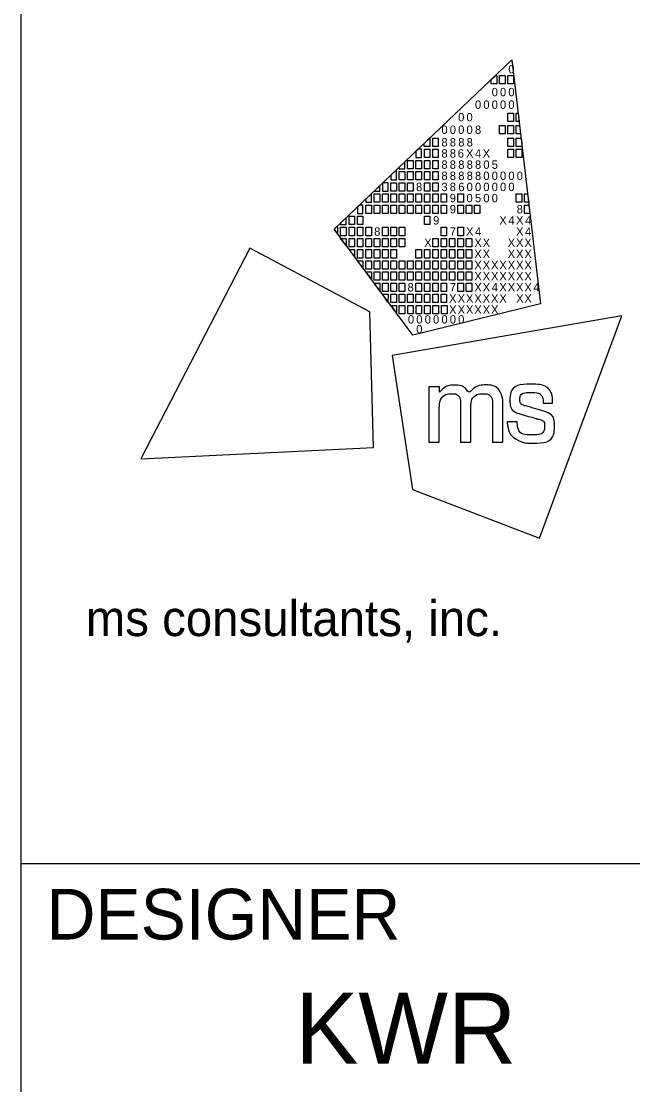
# Model space of a CAD drawing. Extents: x -0.2 to 34, y -4.4 to 17.6.
# Drawn here: x 32 to 33.207, y -2.337 to -0.238 of the extents above; entities that cross this region are included whole.
import ezdxf

# ---------------------------------------------------------------- set-up
doc = ezdxf.new("R2010")
doc.units = 0
doc.layers.add('SH_Border', color=7, linetype='Continuous')
doc.layers.add('SH_Data', color=7, linetype='Continuous')

msp = doc.modelspace()

# ---------------------------------------------------------------- linework, layer by layer
at = {"layer": 'SH_Border'}
for p, q in [((32, -3.9004), (32, 17.0996)), ((32, -1.9004), (33.5, -1.9004))]:
    msp.add_line(p, q, dxfattribs=at)
at = {"layer": 'SH_Data'}
for p, q in [((32.6175, -0.6485), (32.9688, -0.3143)), ((32.9688, -0.3143), (32.9688, -0.3143)), ((32.9688, -0.3143), (33.0253, -0.7953)), ((32.773, -0.8574), (32.6175, -0.6485)), ((33.0253, -0.7953), (32.773, -0.8574)), ((32.75, -0.9004), (32.75, -0.9004))]:
    msp.add_line(p, q, dxfattribs=at)
for points in [[(32.9279, -0.3532), (32.9369, -0.3446), (32.9389, -0.3446), (32.9389, -0.3612), (32.9279, -0.3612)], [(32.9444, -0.3446), (32.9554, -0.3446), (32.9554, -0.3612), (32.9444, -0.3612)], [(32.9609, -0.3446), (32.9719, -0.3446), (32.9719, -0.3612), (32.9609, -0.3612)], [(32.9606, -0.419), (32.9716, -0.419), (32.9716, -0.4355), (32.9606, -0.4355)], [(32.9771, -0.419), (32.9811, -0.419), (32.983, -0.4355), (32.9771, -0.4355)], [(32.9441, -0.4437), (32.9551, -0.4437), (32.9551, -0.4602), (32.9441, -0.4602)], [(32.9606, -0.4437), (32.9716, -0.4437), (32.9716, -0.4602), (32.9606, -0.4602)], [(32.9771, -0.4437), (32.984, -0.4437), (32.9859, -0.4602), (32.9771, -0.4602)], [(32.7953, -0.4793), (32.8064, -0.4688), (32.8064, -0.485), (32.7953, -0.485)], [(32.8123, -0.4685), (32.8233, -0.4685), (32.8233, -0.485), (32.8123, -0.485)], [(32.9606, -0.4685), (32.9716, -0.4685), (32.9716, -0.485), (32.9606, -0.485)], [(32.9771, -0.4685), (32.9869, -0.4685), (32.9881, -0.4786), (32.9881, -0.485), (32.9771, -0.485)], [(32.7958, -0.4905), (32.8068, -0.4905), (32.8068, -0.507), (32.7958, -0.507)], [(32.8123, -0.4905), (32.8233, -0.4905), (32.8233, -0.507), (32.8123, -0.507)], [(32.9606, -0.4905), (32.9716, -0.4905), (32.9716, -0.507), (32.9606, -0.507)], [(32.9771, -0.4905), (32.9881, -0.4905), (32.9881, -0.507), (32.9771, -0.507)], [(32.7627, -0.5125), (32.7737, -0.5125), (32.7737, -0.529), (32.7627, -0.529)], [(32.7793, -0.5125), (32.7903, -0.5125), (32.7903, -0.529), (32.7793, -0.529)], [(32.7958, -0.5125), (32.8068, -0.5125), (32.8068, -0.529), (32.7958, -0.529)], [(32.8123, -0.5125), (32.8233, -0.5125), (32.8233, -0.529), (32.8123, -0.529)], [(32.7462, -0.5346), (32.7572, -0.5346), (32.7572, -0.5511), (32.7462, -0.5511)], [(32.7627, -0.5346), (32.7737, -0.5346), (32.7737, -0.5511), (32.7627, -0.5511)], [(32.7793, -0.5346), (32.7903, -0.5346), (32.7903, -0.5511), (32.7793, -0.5511)], [(32.7958, -0.5346), (32.8068, -0.5346), (32.8068, -0.5511), (32.7958, -0.5511)], [(32.8123, -0.5346), (32.8233, -0.5346), (32.8233, -0.5511), (32.8123, -0.5511)], [(32.7297, -0.5566), (32.7407, -0.5566), (32.7407, -0.5731), (32.7297, -0.5731)], [(32.7462, -0.5566), (32.7572, -0.5566), (32.7572, -0.5731), (32.7462, -0.5731)], [(32.7627, -0.5566), (32.7737, -0.5566), (32.7737, -0.5731), (32.7627, -0.5731)], [(32.7958, -0.5566), (32.8068, -0.5566), (32.8068, -0.5731), (32.7958, -0.5731)], [(32.8123, -0.5566), (32.8233, -0.5566), (32.8233, -0.5731), (32.8123, -0.5731)], [(32.6967, -0.5786), (32.7077, -0.5786), (32.7077, -0.5951), (32.6967, -0.5951)], [(32.7132, -0.5786), (32.7242, -0.5786), (32.7242, -0.5951), (32.7132, -0.5951)], [(32.7297, -0.5786), (32.7407, -0.5786), (32.7407, -0.5951), (32.7297, -0.5951)], [(32.7462, -0.5786), (32.7572, -0.5786), (32.7572, -0.5951), (32.7462, -0.5951)], [(32.7627, -0.5786), (32.7737, -0.5786), (32.7737, -0.5951), (32.7627, -0.5951)], [(32.7793, -0.5786), (32.7903, -0.5786), (32.7903, -0.5951), (32.7793, -0.5951)], [(32.7958, -0.5786), (32.8068, -0.5786), (32.8068, -0.5951), (32.7958, -0.5951)], [(32.8123, -0.5786), (32.8233, -0.5786), (32.8233, -0.5951), (32.8123, -0.5951)], [(32.8288, -0.5786), (32.8398, -0.5786), (32.8398, -0.5951), (32.8288, -0.5951)], [(32.8618, -0.5786), (32.8728, -0.5786), (32.8728, -0.5951), (32.8618, -0.5951)], [(32.9771, -0.5786), (32.9881, -0.5786), (32.9881, -0.5951), (32.9771, -0.5951)], [(32.9935, -0.5786), (32.9998, -0.5786), (33.0018, -0.5951), (32.9935, -0.5951)], [(32.6802, -0.6006), (32.6912, -0.6006), (32.6912, -0.6171), (32.6802, -0.6171)], [(32.6967, -0.6006), (32.7077, -0.6006), (32.7077, -0.6171), (32.6967, -0.6171)], [(32.7132, -0.6006), (32.7242, -0.6006), (32.7242, -0.6171), (32.7132, -0.6171)], [(32.7297, -0.6006), (32.7407, -0.6006), (32.7407, -0.6171), (32.7297, -0.6171)], [(32.7462, -0.6006), (32.7572, -0.6006), (32.7572, -0.6171), (32.7462, -0.6171)], [(32.7627, -0.6006), (32.7737, -0.6006), (32.7737, -0.6171), (32.7627, -0.6171)], [(32.7793, -0.6006), (32.7903, -0.6006), (32.7903, -0.6171), (32.7793, -0.6171)], [(32.7958, -0.6006), (32.8068, -0.6006), (32.8068, -0.6171), (32.7958, -0.6171)], [(32.8123, -0.6006), (32.8233, -0.6006), (32.8233, -0.6171), (32.8123, -0.6171)], [(32.8288, -0.6006), (32.8398, -0.6006), (32.8398, -0.6171), (32.8288, -0.6171)], [(32.8618, -0.6006), (32.8728, -0.6006), (32.8728, -0.6171), (32.8618, -0.6171)], [(32.8783, -0.6006), (32.8893, -0.6006), (32.8893, -0.6171), (32.8783, -0.6171)], [(32.8947, -0.6006), (32.9057, -0.6006), (32.9057, -0.6171), (32.8947, -0.6171)], [(32.9935, -0.6006), (33.0024, -0.6006), (33.0044, -0.6171), (32.9935, -0.6171)], [(32.6471, -0.6226), (32.6581, -0.6226), (32.6581, -0.6391), (32.6471, -0.6391)], [(32.6637, -0.6226), (32.6747, -0.6226), (32.6747, -0.6391), (32.6637, -0.6391)], [(32.7958, -0.6226), (32.8068, -0.6226), (32.8068, -0.6391), (32.7958, -0.6391)], [(32.6306, -0.6446), (32.6416, -0.6446), (32.6416, -0.6612), (32.6306, -0.6612)], [(32.6471, -0.6446), (32.6581, -0.6446), (32.6581, -0.6612), (32.6471, -0.6612)], [(32.6637, -0.6446), (32.6747, -0.6446), (32.6747, -0.6612), (32.6637, -0.6612)], [(32.6802, -0.6446), (32.6912, -0.6446), (32.6912, -0.6612), (32.6802, -0.6612)], [(32.7132, -0.6446), (32.7242, -0.6446), (32.7242, -0.6612), (32.7132, -0.6612)], [(32.7297, -0.6446), (32.7407, -0.6446), (32.7407, -0.6612), (32.7297, -0.6612)], [(32.7462, -0.6446), (32.7572, -0.6446), (32.7572, -0.6612), (32.7462, -0.6612)], [(32.8288, -0.6446), (32.8398, -0.6446), (32.8398, -0.6612), (32.8288, -0.6612)], [(32.8618, -0.6446), (32.8728, -0.6446), (32.8728, -0.6612), (32.8618, -0.6612)], [(32.6306, -0.6667), (32.6416, -0.6667), (32.6416, -0.6804)], [(32.6471, -0.6667), (32.6581, -0.6667), (32.6581, -0.6832), (32.6471, -0.6832)], [(32.6637, -0.6667), (32.6747, -0.6667), (32.6747, -0.6832), (32.6637, -0.6832)], [(32.6802, -0.6667), (32.6912, -0.6667), (32.6912, -0.6832), (32.6802, -0.6832)], [(32.6967, -0.6667), (32.7077, -0.6667), (32.7077, -0.6832), (32.6967, -0.6832)], [(32.7132, -0.6667), (32.7242, -0.6667), (32.7242, -0.6832), (32.7132, -0.6832)], [(32.7297, -0.6667), (32.7407, -0.6667), (32.7407, -0.6832), (32.7297, -0.6832)], [(32.7462, -0.6667), (32.7572, -0.6667), (32.7572, -0.6832), (32.7462, -0.6832)], [(32.8123, -0.6667), (32.8233, -0.6667), (32.8233, -0.6832), (32.8123, -0.6832)], [(32.8288, -0.6667), (32.8398, -0.6667), (32.8398, -0.6832), (32.8288, -0.6832)], [(32.8453, -0.6667), (32.8563, -0.6667), (32.8563, -0.6832), (32.8453, -0.6832)], [(32.8618, -0.6667), (32.8728, -0.6667), (32.8728, -0.6832), (32.8618, -0.6832)], [(32.8783, -0.6667), (32.8893, -0.6667), (32.8893, -0.6832), (32.8783, -0.6832)], [(32.6471, -0.6887), (32.6581, -0.6887), (32.6581, -0.7024)], [(32.6637, -0.6887), (32.6747, -0.6887), (32.6747, -0.7052), (32.6637, -0.7052)], [(32.6802, -0.6887), (32.6912, -0.6887), (32.6912, -0.7052), (32.6802, -0.7052)], [(32.6967, -0.6887), (32.7077, -0.6887), (32.7077, -0.7052), (32.6967, -0.7052)], [(32.7132, -0.6887), (32.7242, -0.6887), (32.7242, -0.7052), (32.7132, -0.7052)], [(32.7297, -0.6887), (32.7407, -0.6887), (32.7407, -0.7052), (32.7297, -0.7052)], [(32.7793, -0.6887), (32.7903, -0.6887), (32.7903, -0.7052), (32.7793, -0.7052)], [(32.7958, -0.6887), (32.8068, -0.6887), (32.8068, -0.7052), (32.7958, -0.7052)], [(32.8123, -0.6887), (32.8233, -0.6887), (32.8233, -0.7052), (32.8123, -0.7052)], [(32.8288, -0.6887), (32.8398, -0.6887), (32.8398, -0.7052), (32.8288, -0.7052)], [(32.8453, -0.6887), (32.8563, -0.6887), (32.8563, -0.7052), (32.8453, -0.7052)], [(32.8618, -0.6887), (32.8728, -0.6887), (32.8728, -0.7052), (32.8618, -0.7052)], [(32.8783, -0.6887), (32.8893, -0.6887), (32.8893, -0.7052), (32.8783, -0.7052)], [(32.6637, -0.7107), (32.6747, -0.7107), (32.6747, -0.7245)], [(32.6747, -0.7107), (32.6747, -0.7107), (32.6747, -0.7107)], [(32.6802, -0.7107), (32.6912, -0.7107), (32.6912, -0.7272), (32.6802, -0.7272)], [(32.6967, -0.7107), (32.7077, -0.7107), (32.7077, -0.7272), (32.6967, -0.7272)], [(32.7132, -0.7107), (32.7242, -0.7107), (32.7242, -0.7272), (32.7132, -0.7272)], [(32.7297, -0.7107), (32.7407, -0.7107), (32.7407, -0.7272), (32.7297, -0.7272)], [(32.7462, -0.7107), (32.7572, -0.7107), (32.7572, -0.7272), (32.7462, -0.7272)], [(32.7627, -0.7107), (32.7737, -0.7107), (32.7737, -0.7272), (32.7627, -0.7272)], [(32.7793, -0.7107), (32.7903, -0.7107), (32.7903, -0.7272), (32.7793, -0.7272)], [(32.7958, -0.7107), (32.8068, -0.7107), (32.8068, -0.7272), (32.7958, -0.7272)], [(32.8123, -0.7107), (32.8233, -0.7107), (32.8233, -0.7272), (32.8123, -0.7272)], [(32.8288, -0.7107), (32.8398, -0.7107), (32.8398, -0.7272), (32.8288, -0.7272)], [(32.8453, -0.7107), (32.8563, -0.7107), (32.8563, -0.7272), (32.8453, -0.7272)], [(32.8618, -0.7107), (32.8728, -0.7107), (32.8728, -0.7272), (32.8618, -0.7272)], [(32.8783, -0.7107), (32.8893, -0.7107), (32.8893, -0.7272), (32.8783, -0.7272)], [(32.6802, -0.7327), (32.6912, -0.7327), (32.6912, -0.7465)], [(32.6967, -0.7327), (32.7077, -0.7327), (32.7077, -0.7492), (32.6967, -0.7492)], [(32.7132, -0.7327), (32.7242, -0.7327), (32.7242, -0.7492), (32.7132, -0.7492)], [(32.7297, -0.7327), (32.7407, -0.7327), (32.7407, -0.7492), (32.7297, -0.7492)], [(32.7462, -0.7327), (32.7572, -0.7327), (32.7572, -0.7492), (32.7462, -0.7492)], [(32.7627, -0.7327), (32.7737, -0.7327), (32.7737, -0.7492), (32.7627, -0.7492)], [(32.7793, -0.7327), (32.7903, -0.7327), (32.7903, -0.7492), (32.7793, -0.7492)], [(32.7958, -0.7327), (32.8068, -0.7327), (32.8068, -0.7492), (32.7958, -0.7492)], [(32.8123, -0.7327), (32.8233, -0.7327), (32.8233, -0.7492), (32.8123, -0.7492)], [(32.8288, -0.7327), (32.8398, -0.7327), (32.8398, -0.7492), (32.8288, -0.7492)], [(32.8453, -0.7327), (32.8563, -0.7327), (32.8563, -0.7492), (32.8453, -0.7492)], [(32.8618, -0.7327), (32.8728, -0.7327), (32.8728, -0.7492), (32.8618, -0.7492)], [(32.8783, -0.7327), (32.8893, -0.7327), (32.8893, -0.7492), (32.8783, -0.7492)], [(32.7077, -0.7699), (32.6965, -0.7547), (32.7077, -0.7547)], [(32.7132, -0.7547), (32.7242, -0.7547), (32.7242, -0.7712), (32.7132, -0.7712)], [(32.7297, -0.7547), (32.7407, -0.7547), (32.7407, -0.7712), (32.7297, -0.7712)], [(32.7462, -0.7547), (32.7572, -0.7547), (32.7572, -0.7712), (32.7462, -0.7712)], [(32.7793, -0.7547), (32.7903, -0.7547), (32.7903, -0.7712), (32.7793, -0.7712)], [(32.7958, -0.7547), (32.8068, -0.7547), (32.8068, -0.7712), (32.7958, -0.7712)], [(32.8123, -0.7547), (32.8233, -0.7547), (32.8233, -0.7712), (32.8123, -0.7712)], [(32.8288, -0.7547), (32.8398, -0.7547), (32.8398, -0.7712), (32.8288, -0.7712)], [(32.8618, -0.7547), (32.8728, -0.7547), (32.8728, -0.7712), (32.8618, -0.7712)], [(32.8783, -0.7547), (32.8893, -0.7547), (32.8893, -0.7712), (32.8783, -0.7712)], [(32.724, -0.7922), (32.7132, -0.7767), (32.7242, -0.7767)], [(32.7297, -0.7768), (32.7407, -0.7768), (32.7407, -0.7933), (32.7297, -0.7933)], [(32.7462, -0.7768), (32.7572, -0.7768), (32.7572, -0.7933), (32.7462, -0.7933)], [(32.7627, -0.7768), (32.7737, -0.7768), (32.7737, -0.7933), (32.7627, -0.7933)], [(32.7793, -0.7768), (32.7903, -0.7768), (32.7903, -0.7933), (32.7793, -0.7933)], [(32.7958, -0.7768), (32.8068, -0.7768), (32.8068, -0.7933), (32.7958, -0.7933)], [(32.8123, -0.7768), (32.8233, -0.7768), (32.8233, -0.7933), (32.8123, -0.7933)], [(32.8288, -0.7768), (32.8398, -0.7768), (32.8398, -0.7933), (32.8288, -0.7933)], [(32.7302, -0.7987), (32.7407, -0.7987), (32.7408, -0.8129)], [(32.7463, -0.7987), (32.7573, -0.7987), (32.7573, -0.8152), (32.7463, -0.8152)], [(32.763, -0.7987), (32.774, -0.7987), (32.774, -0.8152), (32.763, -0.8152)], [(32.7794, -0.7987), (32.7904, -0.7987), (32.7904, -0.8152), (32.7794, -0.8152)], [(32.796, -0.7987), (32.807, -0.7987), (32.807, -0.8152), (32.796, -0.8152)], [(32.8129, -0.7988), (32.8239, -0.7988), (32.8239, -0.8153), (32.8129, -0.8153)], [(32.8296, -0.7988), (32.8406, -0.7988), (32.8406, -0.8153), (32.8296, -0.8153)]]:
    msp.add_lwpolyline(points, close=True, dxfattribs=at)
for points in [[(32.7903, -0.4905), (32.7836, -0.4905), (32.7793, -0.4946), (32.7793, -0.507), (32.7903, -0.507), (32.7903, -0.4905)], [(32.7572, -0.5156), (32.7462, -0.5261), (32.7462, -0.529), (32.7572, -0.529), (32.7572, -0.5156)], [(32.7407, -0.5313), (32.7297, -0.5418), (32.7297, -0.5511), (32.7407, -0.5511), (32.7407, -0.5313)], [(32.7077, -0.5627), (32.6968, -0.5731), (32.7077, -0.5731), (32.7077, -0.5627)], [(32.7242, -0.5566), (32.7141, -0.5566), (32.7132, -0.5575), (32.7132, -0.5731), (32.7242, -0.5731), (32.7242, -0.5566)], [(32.6912, -0.5784), (32.6802, -0.5889), (32.6802, -0.5951), (32.6912, -0.5951), (32.6912, -0.5784)], [(32.6747, -0.6006), (32.6679, -0.6006), (32.6637, -0.6046), (32.6637, -0.6171), (32.6747, -0.6171), (32.6747, -0.6006)], [(32.6416, -0.6256), (32.6306, -0.636), (32.6306, -0.6391), (32.6416, -0.6391), (32.6416, -0.6256)], [(32.6251, -0.6446), (32.6216, -0.6446), (32.6175, -0.6485), (32.6251, -0.6587), (32.6251, -0.6446)], [(32.4512, -0.6856), (32.2359, -1.1016), (32.6956, -1.079), (32.6884, -0.8113), (32.4512, -0.6856)], [(33.0229, -1.2582), (33.1859, -0.819), (32.7324, -0.8975), (32.7722, -1.1623), (33.0229, -1.2582)]]:
    msp.add_lwpolyline(points, dxfattribs=at)
for points in [[(32.8048, -1.0689), (32.8048, -1.0689), (32.8048, -0.9595), (32.8048, -0.9595), (32.8048, -0.9595), (32.8255, -0.9595), (32.8255, -0.9595), (32.8255, -0.9595), (32.8255, -0.9707), (32.8255, -0.9707), (32.8346, -0.9605), (32.8457, -0.956), (32.8555, -0.956), (32.8688, -0.956), (32.8791, -0.9632), (32.8837, -0.9738), (32.8915, -0.9624), (32.905, -0.9558), (32.9166, -0.9558), (32.9325, -0.9558), (32.9451, -0.9654), (32.9494, -0.9792), (32.9494, -0.9792), (32.9494, -0.9792), (32.9494, -0.9793), (32.9501, -0.9815), (32.9506, -0.9832), (32.9506, -0.9934), (32.9506, -0.9934), (32.9506, -1.069), (32.9506, -1.069), (32.9506, -1.069), (32.9303, -1.069), (32.9303, -1.069), (32.9303, -1.069), (32.9303, -0.9956), (32.9303, -0.9956), (32.9303, -0.9803), (32.9219, -0.973), (32.911, -0.973), (32.8995, -0.973), (32.8879, -0.9834), (32.8879, -1.0003), (32.8879, -1.0003), (32.8879, -1.0689), (32.8879, -1.0689), (32.8879, -1.0689), (32.8674, -1.0689), (32.8674, -1.0689), (32.8674, -1.0689), (32.8674, -0.9945), (32.8674, -0.9945), (32.8674, -0.9801), (32.8588, -0.973), (32.8496, -0.973), (32.8384, -0.973), (32.8254, -0.9834), (32.8254, -1.0042), (32.8254, -1.0042), (32.8254, -1.0689), (32.8254, -1.0689), (32.8254, -1.0689), (32.8048, -1.0689), (32.8048, -1.0689)], [(32.9595, -1.0296), (32.9595, -1.0296), (32.9595, -1.0287), (32.9595, -1.0287), (32.9595, -1.0287), (32.9603, -1.0287), (32.9603, -1.0287), (32.9603, -1.0287), (32.9783, -1.0287), (32.9783, -1.0287), (32.9783, -1.0287), (32.9789, -1.0287), (32.9789, -1.0287), (32.9789, -1.0287), (32.979, -1.0294), (32.979, -1.0294), (32.9803, -1.045), (32.9887, -1.0544), (33.009, -1.0544), (33.0273, -1.0544), (33.0333, -1.045), (33.0333, -1.0373), (33.0333, -1.0273), (33.0256, -1.0247), (33.0175, -1.0224), (33.0175, -1.0224), (32.987, -1.0137), (32.987, -1.0137), (32.972, -1.0095), (32.9648, -0.9986), (32.9648, -0.9862), (32.9648, -0.9701), (32.9768, -0.9543), (33.0052, -0.9543), (33.0348, -0.9543), (33.0489, -0.9719), (33.0489, -0.991), (33.0489, -0.991), (33.0489, -0.9917), (33.0489, -0.9917), (33.0489, -0.9917), (33.0482, -0.9917), (33.0482, -0.9917), (33.0482, -0.9917), (33.0312, -0.9917), (33.0312, -0.9917), (33.0312, -0.9917), (33.0305, -0.9917), (33.0305, -0.9917), (33.0305, -0.9917), (33.0305, -0.991), (33.0305, -0.991), (33.0301, -0.9796), (33.0226, -0.9705), (33.0056, -0.9705), (32.9891, -0.9705), (32.9843, -0.9787), (32.9843, -0.9847), (32.9843, -0.9896), (32.9869, -0.9945), (32.9959, -0.9971), (32.9959, -0.9971), (33.0255, -1.0056), (33.0255, -1.0056), (33.0462, -1.0116), (33.0527, -1.0227), (33.0527, -1.0365), (33.0527, -1.0542), (33.041, -1.0706), (33.0087, -1.0706), (32.9952, -1.0706), (32.9877, -1.0683), (32.9823, -1.0656), (32.969, -1.059), (32.9609, -1.0469), (32.9595, -1.0296)]]:
    msp.add_open_spline(points, degree=3, dxfattribs=at)

# ---------------------------------------------------------------- texts
for s, height, p in [('0', 0.0165, (32.9617, -0.3407)), ('0', 0.0165, (32.9288, -0.3859)), ('0', 0.0165, (32.9452, -0.3859)), ('0', 0.0165, (32.9617, -0.3859)), ('0', 0.0165, (32.8958, -0.4107)), ('0', 0.0165, (32.9123, -0.4107)), ('0', 0.0165, (32.9288, -0.4107)), ('0', 0.0165, (32.9452, -0.4107)), ('0', 0.0165, (32.9617, -0.4107)), ('0', 0.0165, (32.8625, -0.4355)), ('0', 0.0165, (32.879, -0.4355)), ('0', 0.0165, (32.8295, -0.4602)), ('0', 0.0165, (32.846, -0.4602)), ('0', 0.0165, (32.8625, -0.4602)), ('0', 0.0165, (32.879, -0.4602)), ('8', 0.0165, (32.8958, -0.4602)), ('8', 0.0165, (32.8295, -0.485)), ('8', 0.0165, (32.846, -0.485)), ('8', 0.0165, (32.8628, -0.485)), ('8', 0.0165, (32.8793, -0.485)), ('8', 0.0165, (32.8295, -0.507)), ('8', 0.0165, (32.846, -0.507)), ('6', 0.0165, (32.8618, -0.507)), ('X', 0.0165, (32.8781, -0.507)), ('4', 0.0165, (32.8958, -0.507)), ('X', 0.0165, (32.911, -0.507)), ('8', 0.0165, (32.8295, -0.5291)), ('8', 0.0165, (32.846, -0.5291)), ('8', 0.0165, (32.8628, -0.5291)), ('8', 0.0165, (32.8794, -0.5291)), ('8', 0.0165, (32.8958, -0.5291)), ('0', 0.0165, (32.9123, -0.5291)), ('5', 0.0165, (32.9287, -0.5291)), ('8', 0.0165, (32.8295, -0.5511)), ('8', 0.0165, (32.846, -0.5511)), ('8', 0.0165, (32.8628, -0.5511)), ('8', 0.0165, (32.8794, -0.5511)), ('8', 0.0165, (32.8958, -0.5511)), ('0', 0.0165, (32.9123, -0.5511)), ('0', 0.0165, (32.9288, -0.5511)), ('0', 0.0165, (32.9452, -0.5511)), ('0', 0.0165, (32.9617, -0.5511)), ('0', 0.0165, (32.9782, -0.5511)), ('8', 0.0165, (32.7793, -0.5731)), ('3', 0.0165, (32.8295, -0.5731)), ('8', 0.0165, (32.846, -0.5731)), ('6', 0.0165, (32.8629, -0.5731)), ('0', 0.0165, (32.8793, -0.5731)), ('0', 0.0165, (32.8958, -0.5731)), ('0', 0.0165, (32.9123, -0.5731)), ('0', 0.0165, (32.9288, -0.5731)), ('0', 0.0165, (32.9452, -0.5731)), ('0', 0.0165, (32.9617, -0.5731)), ('9', 0.0165, (32.846, -0.5951)), ('0', 0.0165, (32.879, -0.5951)), ('5', 0.0165, (32.8957, -0.5951)), ('0', 0.0165, (32.9123, -0.5951)), ('0', 0.0165, (32.9288, -0.5951)), ('9', 0.0165, (32.846, -0.6171)), ('8', 0.0165, (32.9781, -0.6171)), ('9', 0.0165, (32.813, -0.6391)), ('X', 0.0165, (32.9439, -0.6391)), ('4', 0.0165, (32.9617, -0.6391)), ('X', 0.0165, (32.9769, -0.6391)), ('4', 0.0165, (32.9946, -0.6391)), ('8', 0.0165, (32.6967, -0.6612)), ('7', 0.0165, (32.846, -0.6612)), ('X', 0.0165, (32.8781, -0.6612)), ('4', 0.0165, (32.8958, -0.6612)), ('X', 0.0165, (32.9769, -0.6612)), ('4', 0.0165, (32.9946, -0.6612)), ('X', 0.0165, (32.7955, -0.6832)), ('X', 0.0165, (32.8945, -0.6832)), ('X', 0.0165, (32.911, -0.6832)), ('X', 0.0165, (32.9604, -0.6832)), ('X', 0.0165, (32.9769, -0.6832)), ('X', 0.0165, (32.9933, -0.6832)), ('X', 0.0165, (32.8945, -0.7052)), ('X', 0.0165, (32.911, -0.7052)), ('X', 0.0165, (32.9604, -0.7052)), ('X', 0.0165, (32.9769, -0.7052)), ('X', 0.0165, (32.9933, -0.7052)), ('X', 0.0165, (32.8945, -0.7272)), ('X', 0.0165, (32.911, -0.7272)), ('X', 0.0165, (32.9274, -0.7272)), ('X', 0.0165, (32.9439, -0.7272)), ('X', 0.0165, (32.9604, -0.7272)), ('X', 0.0165, (32.9769, -0.7272)), ('X', 0.0165, (32.9933, -0.7272)), ('X', 0.0165, (32.8945, -0.7492)), ('X', 0.0165, (32.911, -0.7492)), ('X', 0.0165, (32.9274, -0.7492)), ('X', 0.0165, (32.9439, -0.7492)), ('X', 0.0165, (32.9604, -0.7492)), ('X', 0.0165, (32.9769, -0.7492)), ('X', 0.0165, (32.9933, -0.7492)), ('8', 0.0165, (32.7627, -0.7712)), ('7', 0.0165, (32.846, -0.7712)), ('X', 0.0165, (32.8945, -0.7712)), ('X', 0.0165, (32.911, -0.7712)), ('4', 0.0165, (32.9288, -0.7712)), ('X', 0.0165, (32.9439, -0.7712)), ('X', 0.0165, (32.9604, -0.7712)), ('X', 0.0165, (32.9769, -0.7712)), ('X', 0.0165, (32.9933, -0.7712)), ('4', 0.0165, (33.0111, -0.7712)), ('X', 0.0165, (32.8447, -0.7933)), ('X', 0.0165, (32.8616, -0.7933)), ('X', 0.0165, (32.878, -0.7933)), ('X', 0.0165, (32.8945, -0.7933)), ('X', 0.0165, (32.911, -0.7933)), ('X', 0.0165, (32.9274, -0.7933)), ('X', 0.0165, (32.9439, -0.7933)), ('X', 0.0165, (32.9771, -0.7933)), ('X', 0.0165, (32.9933, -0.7933)), ('0', 0.0165, (32.7634, -0.8346)), ('0', 0.0165, (32.7799, -0.8346)), ('0', 0.0165, (32.7965, -0.8346)), ('0', 0.0165, (32.813, -0.8346)), ('0', 0.0165, (32.8295, -0.8346)), ('X', 0.0165, (32.8447, -0.8153)), ('0', 0.0165, (32.846, -0.8346)), ('X', 0.0165, (32.8616, -0.8153)), ('0', 0.0165, (32.8625, -0.8346)), ('X', 0.0165, (32.878, -0.8153)), ('X', 0.0165, (32.8945, -0.8153)), ('X', 0.0165, (32.911, -0.8153)), ('X', 0.0165, (32.9274, -0.8153)), ('0', 0.0165, (32.7799, -0.8538)), ('ms consultants, inc.', 0.07, (32.1273, -1.4515))]:
    msp.add_text(s, height=height, rotation=360, dxfattribs=at).set_placement(p)
for s, height, p in [('DESIGNER', 0.1, (32.05, -2.0504)), ('KWR', 0.14, (32.5407, -2.2954))]:
    msp.add_text(s, height=height, dxfattribs=at).set_placement(p)

doc.saveas('drawing.dxf')
